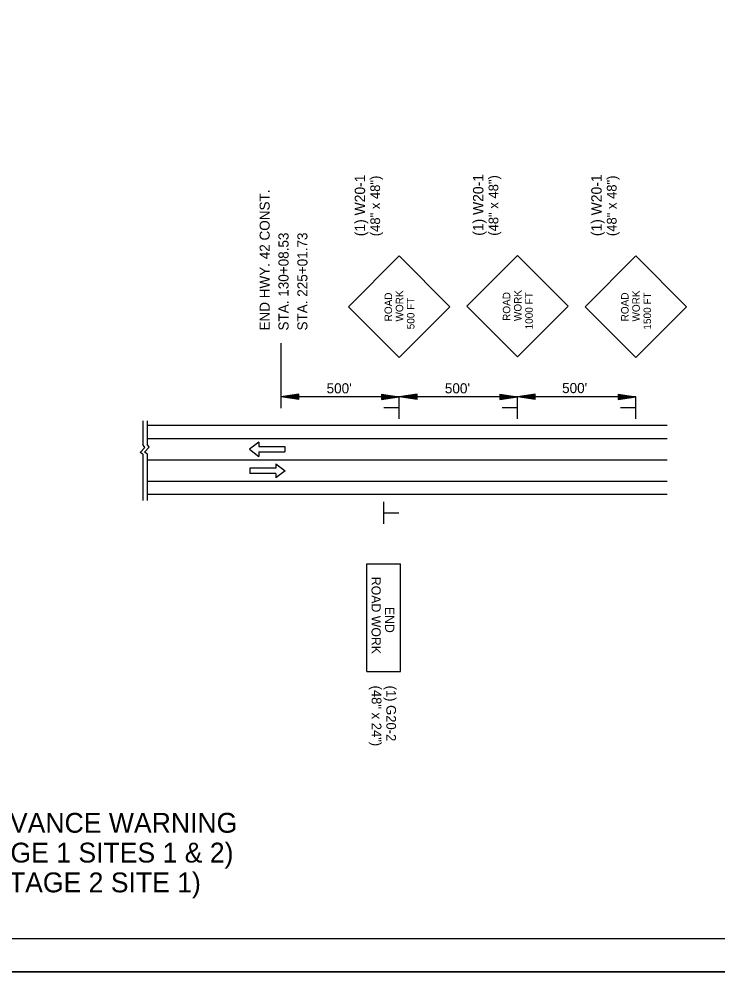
# Model space of a CAD drawing. Extents: x 1678017 to 1687792, y 404433 to 413488.
# Drawn here: x 1680249 to 1680671, y 410689 to 411265 of the extents above; entities that cross this region are included whole.
import ezdxf

# ---------------------------------------------------------------- set-up
doc = ezdxf.new("R2010")
doc.units = 0
for name, color, linetype in [('Default', 7, 'Continuous'), ('S_BUILDING', 7, 'Continuous'), ('S_GRAVEL_ROAD', 7, 'Continuous'), ('S_MSC_PT_SYM', 7, 'Continuous'), ('S_STREAM', 7, 'Continuous'), ('S_TELEPHONE_UTILITIES', 7, 'Continuous')]:
    doc.layers.add(name, color=color, linetype=linetype)

msp = doc.modelspace()

# ---------------------------------------------------------------- linework, layer by layer
at = {"layer": 'Default'}
for p, q in [((1680406.87, 411069.32), (1680406.87, 411030.03)), ((1680478.3, 411036.87), (1680406.87, 411036.87)), ((1680549.73, 411036.87), (1680478.3, 411036.87)), ((1680621.16, 411036.87), (1680549.73, 411036.87)), ((1680323.44, 411022.33), (1680323.44, 411008.12)), ((1680326.02, 411022.51), (1680326.02, 411008.31)), ((1680640.02, 411011.56), (1680326.02, 411011.56)), ((1680393.47, 411009.5), (1680387.91, 411005.22)), ((1680393.47, 411009.5), (1680393.47, 411006.82)), ((1680323.44, 411002.25), (1680323.44, 410974.36)), ((1680326.02, 411002.43), (1680326.02, 410974.36)), ((1680387.91, 411005.22), (1680393.47, 411000.93)), ((1680393.47, 411006.82), (1680409.24, 411006.82)), ((1680393.47, 411003.61), (1680409.24, 411003.61)), ((1680393.47, 411003.61), (1680393.47, 411000.93)), ((1680409.24, 411006.82), (1680409.24, 411003.61)), ((1680640.02, 410998.7), (1680326.02, 410998.7)), ((1680403.84, 410996.53), (1680403.84, 410993.85)), ((1680403.84, 410996.53), (1680409.4, 410992.25)), ((1680403.84, 410993.85), (1680388.07, 410993.85)), ((1680388.07, 410993.85), (1680388.07, 410990.64)), ((1680403.84, 410990.64), (1680388.07, 410990.64)), ((1680409.4, 410992.25), (1680403.84, 410987.96)), ((1680403.84, 410990.64), (1680403.84, 410987.96)), ((1680640.02, 410985.85), (1680326.02, 410985.85))]:
    msp.add_line(p, q, dxfattribs=at)
for points in [[(1680323.44, 411002.25), (1680321.79, 411003.23), (1680324.74, 411006.27), (1680323.44, 411008.12)], [(1680326.02, 411002.43), (1680324.37, 411003.42), (1680327.32, 411006.46), (1680326.02, 411008.31)]]:
    msp.add_lwpolyline(points, dxfattribs=at)
at = {"layer": 'S_BUILDING'}
msp.add_line((1681397.07, 410709.37), (1679816.17, 410709.37), dxfattribs=at)
at = {"layer": 'S_GRAVEL_ROAD'}
for p, q in [((1680478.3, 411122.03), (1680447.65, 411091.38)), ((1680478.3, 411122.03), (1680508.93, 411091.38)), ((1680549.73, 411122.29), (1680519.08, 411091.64)), ((1680549.73, 411122.29), (1680580.35, 411091.64)), ((1680621.16, 411122.03), (1680590.5, 411091.38)), ((1680621.16, 411122.03), (1680651.79, 411091.38)), ((1680447.65, 411091.38), (1680478.3, 411060.72)), ((1680508.93, 411091.38), (1680478.3, 411060.72)), ((1680519.08, 411091.64), (1680549.73, 411060.99)), ((1680580.35, 411091.64), (1680549.73, 411060.99)), ((1680590.5, 411091.38), (1680621.16, 411060.72)), ((1680651.79, 411091.38), (1680621.16, 411060.72)), ((1680478.3, 411023.63), (1680478.3, 411036.87)), ((1680549.73, 411023.63), (1680549.73, 411036.87)), ((1680621.16, 411023.63), (1680621.16, 411036.87)), ((1680478.11, 411030.22), (1680469.07, 411030.22)), ((1680549.53, 411030.22), (1680540.5, 411030.22)), ((1680620.96, 411030.22), (1680611.93, 411030.22)), ((1680468.88, 410960.19), (1680468.88, 410973.42)), ((1680469.07, 410966.77), (1680478.11, 410966.77)), ((1680458.65, 410870.97), (1680458.65, 410936.06)), ((1680458.65, 410936.06), (1680479.1, 410936.06)), ((1680479.1, 410870.97), (1680479.1, 410936.06)), ((1680458.65, 410870.97), (1680479.1, 410870.97))]:
    msp.add_line(p, q, dxfattribs=at)
at = {"layer": 'S_MSC_PT_SYM'}
for p, q in [((1680417.58, 411038.48), (1680406.87, 411036.87)), ((1680417.58, 411035.26), (1680406.87, 411036.87)), ((1680417.58, 411038.21), (1680408.66, 411036.87)), ((1680417.58, 411035.53), (1680408.66, 411036.87)), ((1680417.58, 411037.94), (1680410.5, 411036.87)), ((1680417.58, 411035.8), (1680410.5, 411036.87)), ((1680417.58, 411037.67), (1680412.29, 411036.87)), ((1680417.58, 411036.07), (1680412.29, 411036.87)), ((1680417.58, 411037.4), (1680414.1, 411036.87)), ((1680417.58, 411036.35), (1680414.1, 411036.87)), ((1680417.58, 411037.12), (1680415.89, 411036.87)), ((1680417.58, 411036.62), (1680415.89, 411036.87)), ((1680417.58, 411035.26), (1680417.58, 411038.48)), ((1680467.58, 411038.48), (1680478.3, 411036.87)), ((1680467.58, 411038.48), (1680467.58, 411035.26)), ((1680467.58, 411038.21), (1680476.51, 411036.87)), ((1680467.58, 411037.94), (1680474.67, 411036.87)), ((1680467.58, 411037.67), (1680472.88, 411036.87)), ((1680467.58, 411037.39), (1680471.07, 411036.87)), ((1680467.58, 411037.12), (1680469.28, 411036.87)), ((1680467.58, 411035.26), (1680478.3, 411036.87)), ((1680467.58, 411036.35), (1680471.07, 411036.87)), ((1680467.58, 411035.8), (1680474.67, 411036.87)), ((1680467.58, 411035.53), (1680476.51, 411036.87)), ((1680467.58, 411036.07), (1680472.88, 411036.87)), ((1680467.58, 411036.62), (1680469.28, 411036.87)), ((1680489.01, 411038.48), (1680478.3, 411036.87)), ((1680489.01, 411035.26), (1680478.3, 411036.87)), ((1680489.01, 411038.21), (1680480.09, 411036.87)), ((1680489.01, 411035.53), (1680480.09, 411036.87)), ((1680489.01, 411037.94), (1680481.93, 411036.87)), ((1680489.01, 411035.8), (1680481.93, 411036.87)), ((1680489.01, 411037.67), (1680483.71, 411036.87)), ((1680489.01, 411036.07), (1680483.71, 411036.87)), ((1680489.01, 411037.4), (1680485.53, 411036.87)), ((1680489.01, 411036.35), (1680485.53, 411036.87)), ((1680489.01, 411037.12), (1680487.32, 411036.87)), ((1680489.01, 411036.62), (1680487.32, 411036.87)), ((1680489.01, 411035.26), (1680489.01, 411038.48)), ((1680539.01, 411038.48), (1680549.73, 411036.87)), ((1680539.01, 411038.48), (1680539.01, 411035.26)), ((1680539.01, 411038.21), (1680547.94, 411036.87)), ((1680539.01, 411037.94), (1680546.1, 411036.87)), ((1680539.01, 411037.67), (1680544.31, 411036.87)), ((1680539.01, 411037.39), (1680542.5, 411036.87)), ((1680539.01, 411037.12), (1680540.71, 411036.87)), ((1680539.01, 411035.26), (1680549.73, 411036.87)), ((1680539.01, 411036.35), (1680542.5, 411036.87)), ((1680539.01, 411035.8), (1680546.1, 411036.87)), ((1680539.01, 411035.53), (1680547.94, 411036.87)), ((1680539.01, 411036.07), (1680544.31, 411036.87)), ((1680539.01, 411036.62), (1680540.71, 411036.87)), ((1680560.44, 411038.48), (1680549.73, 411036.87)), ((1680560.44, 411035.26), (1680549.73, 411036.87)), ((1680560.44, 411038.21), (1680551.52, 411036.87)), ((1680560.44, 411035.53), (1680551.52, 411036.87)), ((1680560.44, 411037.94), (1680553.36, 411036.87)), ((1680560.44, 411035.8), (1680553.36, 411036.87)), ((1680560.44, 411037.67), (1680555.14, 411036.87)), ((1680560.44, 411036.07), (1680555.14, 411036.87)), ((1680560.44, 411037.4), (1680556.96, 411036.87)), ((1680560.44, 411036.35), (1680556.96, 411036.87)), ((1680560.44, 411037.12), (1680558.75, 411036.87)), ((1680560.44, 411036.62), (1680558.75, 411036.87)), ((1680560.44, 411035.26), (1680560.44, 411038.48)), ((1680610.44, 411038.48), (1680621.16, 411036.87)), ((1680610.44, 411038.48), (1680610.44, 411035.26)), ((1680610.44, 411038.21), (1680619.37, 411036.87)), ((1680610.44, 411037.94), (1680617.52, 411036.87)), ((1680610.44, 411037.67), (1680615.74, 411036.87)), ((1680610.44, 411037.39), (1680613.92, 411036.87)), ((1680610.44, 411037.12), (1680612.13, 411036.87)), ((1680610.44, 411035.26), (1680621.16, 411036.87)), ((1680610.44, 411036.35), (1680613.92, 411036.87)), ((1680610.44, 411035.8), (1680617.52, 411036.87)), ((1680610.44, 411035.53), (1680619.37, 411036.87)), ((1680610.44, 411036.07), (1680615.74, 411036.87)), ((1680610.44, 411036.62), (1680612.13, 411036.87))]:
    msp.add_line(p, q, dxfattribs=at)
at = {"layer": 'S_STREAM'}
for p, q in [((1680478.3, 411036.87), (1680427.24, 411036.87)), ((1680467.58, 411038.48), (1680478.3, 411036.87)), ((1680467.58, 411038.48), (1680467.58, 411035.26)), ((1680467.58, 411038.21), (1680476.51, 411036.87)), ((1680467.58, 411037.94), (1680474.67, 411036.87)), ((1680467.58, 411037.67), (1680472.88, 411036.87)), ((1680467.58, 411037.39), (1680471.07, 411036.87)), ((1680467.58, 411037.12), (1680469.28, 411036.87)), ((1680467.58, 411035.26), (1680478.3, 411036.87)), ((1680467.58, 411036.35), (1680471.07, 411036.87)), ((1680467.58, 411035.8), (1680474.67, 411036.87)), ((1680467.58, 411035.53), (1680476.51, 411036.87)), ((1680467.58, 411036.07), (1680472.88, 411036.87)), ((1680467.58, 411036.62), (1680469.28, 411036.87)), ((1679754.17, 410689.48), (1681420.84, 410689.48))]:
    msp.add_line(p, q, dxfattribs=at)
for points in [[(1679754.14, 411756.14), (1681420.84, 411756.14), (1681420.84, 410689.45), (1679754.14, 410689.45)], [(1680985.77, 411736.67), (1681083.87, 411736.67), (1681083.87, 411687.27), (1681164.43, 411687.27), (1681280.43, 411687.27), (1681280.43, 411565.61), (1681397.07, 411565.61), (1681397.07, 410709.37), (1679816.17, 410709.37), (1679816.17, 411736.67)]]:
    msp.add_lwpolyline(points, close=True, dxfattribs=at)
at = {"layer": 'S_TELEPHONE_UTILITIES'}
for p, q in [((1680640.02, 411019.56), (1680326.02, 411019.56)), ((1680640.02, 410977.85), (1680326.02, 410977.85))]:
    msp.add_line(p, q, dxfattribs=at)

# ---------------------------------------------------------------- texts
at = {"layer": 'Default'}
for s, rotation, p in [('END HWY. 42 CONST.', 90, (1680400.07, 411076.99)), ('STA. 130+08.53', 90, (1680411.45, 411076.99)), ('STA. 225+01.73', 90, (1680422.84, 411076.99)), ("500'", 360, (1680434.42, 411039.02)), ("500'", 360, (1680505.85, 411039.02)), ("500'", 360, (1680576.64, 411039.18))]:
    msp.add_text(s, height=6.1, rotation=rotation, dxfattribs=at).set_placement(p)
at = {"layer": 'S_GRAVEL_ROAD'}
for s, height, rotation, p in [('(1) W20-1', 6.273, 90.02584, (1680457.68, 411133.95)), ('(48" x 48")', 5.88, 90.02584, (1680466.71, 411133.95)), ('(1) W20-1', 6.273, 90.02584, (1680529.11, 411134.24)), ('(48" x 48")', 5.88, 90.02584, (1680538.14, 411134.24)), ('(1) W20-1', 6.273, 90.02584, (1680600.54, 411134.01)), ('(48" x 48")', 5.88, 90.02584, (1680609.56, 411134.02)), ('WORK', 4.515, 90.00004, (1680480.7, 411082.43)), ('ROAD', 4.516, 90.00045, (1680545.36, 411082.79)), ('WORK', 4.515, 90.00004, (1680552.13, 411082.7)), ('1000 FT', 4.516, 90.00057, (1680558.91, 411077.65)), ('WORK', 4.515, 90.00004, (1680623.56, 411082.43)), ('1500 FT', 4.516, 90.00057, (1680630.34, 411077.56)), ('ROAD', 4.516, 90.00045, (1680473.93, 411082.52)), (' 500 FT', 4.516, 90.00057, (1680487.48, 411076.05)), ('ROAD', 4.516, 90.00045, (1680616.79, 411082.52)), ('ROAD WORK', 5.557, 270, (1680461.54, 410928.19)), ('END', 5.557, 270, (1680469.74, 410910.05)), ('(48" x 24")', 5.88, 270, (1680461.65, 410862.47)), ('(1) G20-2', 5.881, 270, (1680470.46, 410862.47))]:
    msp.add_text(s, height=height, rotation=rotation, dxfattribs=at).set_placement(p)
at = {"layer": 'S_MSC_PT_SYM'}
for s, p in [('ADVANCE WARNING ', (1680220.89, 410773.55)), ('(STAGE 1 SITES 1 & 2)', (1680206.95, 410755.55)), ('(STAGE 2 SITE 1)', (1680226.51, 410737.55))]:
    msp.add_text(s, height=12, rotation=360, dxfattribs=at).set_placement(p)

doc.saveas('drawing.dxf')
